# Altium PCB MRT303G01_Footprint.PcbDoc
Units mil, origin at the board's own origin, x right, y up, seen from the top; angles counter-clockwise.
Board outline 6000 x 4000 mil, 2 copper layers (Top Layer, Bottom Layer); 1 components, 0 nets, 10 pads, 0 vias.
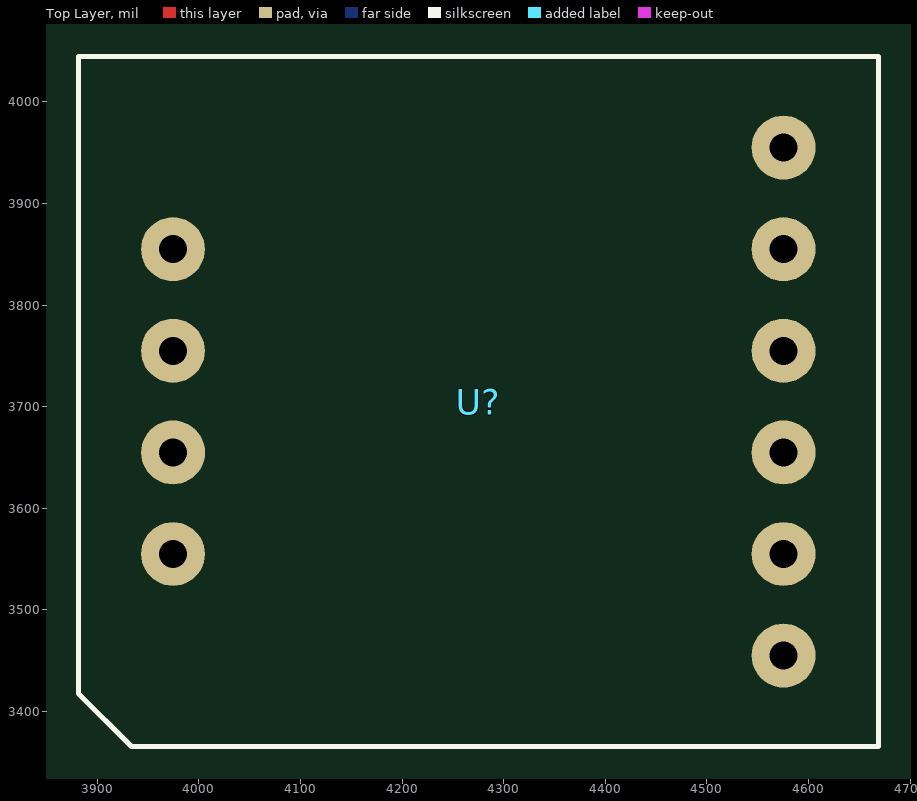
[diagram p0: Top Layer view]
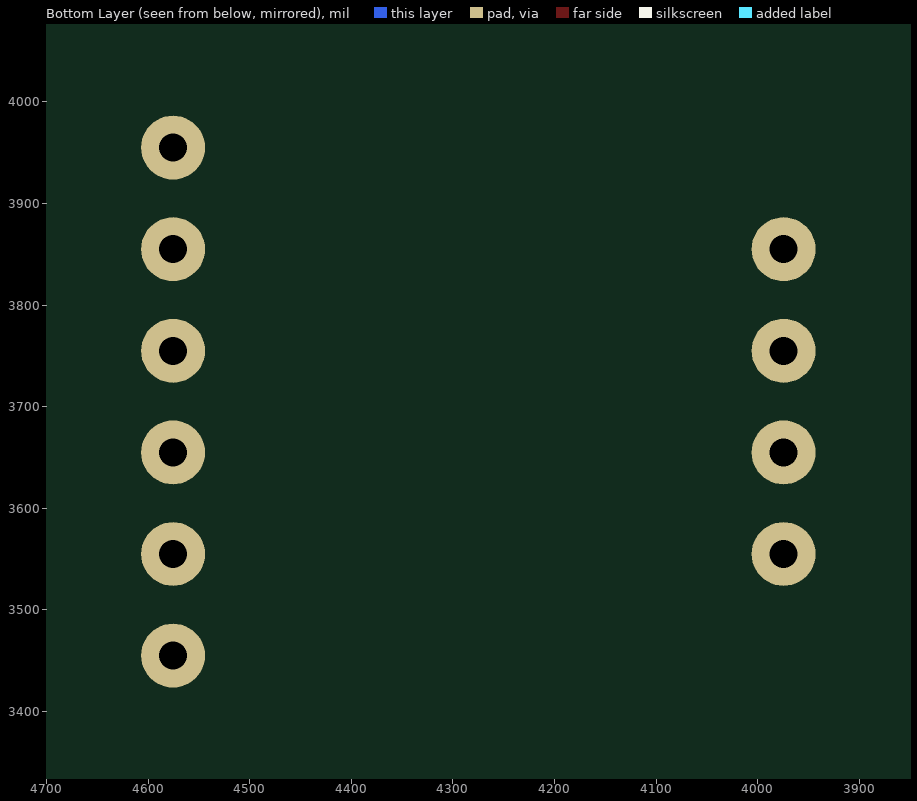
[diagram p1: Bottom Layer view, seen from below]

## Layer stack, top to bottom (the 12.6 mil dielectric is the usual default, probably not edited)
Top Solder: solder mask 0.4, Solder Resist, Dk 3.5
Top Layer: signal copper 1.4
Dielectric 1: dielectric 12.6, FR-4, Dk 4.8
Bottom Layer: signal copper 1.4
Bottom Solder: solder mask 0.4, Solder Resist, Dk 3.5

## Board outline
1000,1000 7000,1000 7000,5000 1000,5000

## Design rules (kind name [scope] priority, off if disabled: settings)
Clearance [All] p1: gap=10 ignorepadtopadclearanceinfootprint=FALSE except(0: Arc-Hole Track-Hole SMDPad-Hole THPad-Hole Via-Hole Fill-Hole Poly-Hole Region-Hole Text-Hole)
PolygonConnect [All] p1: connectstyle=Relief reliefconductorwidth=10 reliefentries=4 polygonreliefangle="90 Angle" airgapwidth=10
RoutingVias [All] p1: holewidth=28 width=50 viastyle="Through Hole" minholewidth=28 minwidth=50 maxholewidth=28 maxwidth=50
SolderMaskExpansion [All] p1: expansion=4
Width [All] p1: maxlimit=10 minlimit=10 preferedwidth=10
30 further rules are at their usual default settings.

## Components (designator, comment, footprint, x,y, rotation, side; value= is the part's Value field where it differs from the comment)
U? "MRT303G01" MRT303G01 4275,3705 r0 top (schematic designator U2)

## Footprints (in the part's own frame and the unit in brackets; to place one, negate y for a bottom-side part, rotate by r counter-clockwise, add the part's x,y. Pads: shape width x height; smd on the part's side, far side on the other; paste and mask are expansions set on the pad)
MRT303G01 [mm]
  round 1.6 hole 0.7: 1(-7.632,-3.81) 2(-7.632,-1.27) 3(-7.633,1.27) 4(-7.633,3.81) 5(7.633,6.35) 6(7.633,3.81) 7(7.633,1.27) 8(7.633,-1.27) 9(7.633,-3.81) 10(7.633,-6.35)
  silkscreen extent -10,-8.63 10,8.63

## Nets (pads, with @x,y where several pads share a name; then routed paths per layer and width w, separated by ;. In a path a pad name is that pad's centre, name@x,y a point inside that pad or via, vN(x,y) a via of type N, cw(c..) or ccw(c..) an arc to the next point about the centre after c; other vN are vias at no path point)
pads on no net: U?.1 U?.2 U?.3 U?.4 U?.5 U?.6 U?.7 U?.8 U?.9 U?.10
